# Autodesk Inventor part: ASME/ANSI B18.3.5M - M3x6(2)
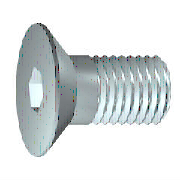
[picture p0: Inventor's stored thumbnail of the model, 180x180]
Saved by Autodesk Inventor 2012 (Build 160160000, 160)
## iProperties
Created: 2011-02
Part Number: ASME/ANSI B18.3.5M - M3x6(2)
Material: Steel, Mild
Description: Broached Hexagon Socket Flat Countersunk Head Cap Screws - Metric
Document SubType Name: Modeling
Standard: ASME/ANSI B18.3.5M
Designer: jrr70267
Standard Revision: 1986
Standards Organization: ANSI
Language: en-US
Size Designation: M3x6
Categories: <MemberInstance><Categories><Category DisplayName="Fasteners" InternalName="e4da775c-781d-43d5-af7c-5136215cf5a6" Mnemonic="FSTN"><Category DisplayName="Bolts"
Density: 7.86 g/cm^3
IsCustomPart: 0
Author: jrr70267
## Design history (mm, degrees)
sketch "Sketch2"
  geometry: L1 (0, -6)-(-1.5, -6); L2 (0, 0)-(0, -6); L3 (-2.675, 0)-(0, 0); L4 (-2.675, -0.685)-(-2.675, 0); L5 (-1.5, -1.86)-(-2.675, -0.685); L6 (-1.5, -6)-(-1.5, -1.86); L7 (0, 0)-(0, -6); 1 further point
  constraints: 14 end point, 3 vertical, 2 horizontal, 1 coincident
  dimensions: "d2" = 45 deg angle of L5 L2; "d4" = 1.5 distance of L1.start L1.end (= 0.5 x NND); "d6" = 2.675 distance of L3.start L2.start (= 0.5 x ParA); "d8" = 1.86 vertical distance of L2.start L5.start (= ParH); "d10" = 6 distance of L2.start L1.start (= NLG)
fillet "Fillet1" dims "d24" = 0.25 (= Rr)
chamfer "Chamfer1" distance "d25" = 0.25 (= 0.5 x PTC); stored, may be unused: second distance "d26" = 0.25 (= 0.5 x PTC), angle "d41" = 45 deg
sketch "Sketch4"
  geometry: L1 (-1, -0.577)-(-1, 0.577); L2 (-1, 0.577)-(0, 1.155); L3 (0, 1.155)-(1, 0.577); L4 (1, 0.577)-(1, -0.577); L5 (1, -0.577)-(0, -1.155); L6 (0, -1.155)-(-1, -0.577); C1 r 2.675 at (0, 0) reference; C2 r 1 at (0, 0)
  constraints: 12 end point, 6 tangent, 4 equal length, 1 centre point, 1 coincident, 1 parallel, 1 vertical
  dimensions: "d27" = 2 diameter of C2 (= ParJ)
extrude "Extrusion2" cut sketch "Sketch4" distance "d39" = 1.1 (= Tt); taper "d40" = 0 deg
node "MSC_A1"
node "MSC_PF1"
node "MSC_PT1"
body "Solid1"
revolve "Revolution1" stored, may be unused: angle "d11" = 360 deg
extrude "Extrusion1" cut sketch "Sketch4" distance "d28" = 1.1 (= Tt); taper "d29" = 0 deg
thread "Thread1" dims "d31" = 3.14 (= Lt), "d32" = 0
sketch "Sketch5"
  geometry: C1 r 2.675 at (0, 0) reference; C2 r 1.01 at (0, 0)
  constraints: 1 centre point, 1 coincident
  dimensions: "d38" = 2.02 diameter of C2 (= 1.01 x ParJ)
other parameters: "NND" = 3 [user parameter; used in 2 equation terms], "NLG" = 6 [user parameter; used in 1 equation term], "PTC" = 0.5 [user parameter; used in 2 equation terms], "ParA" = 5.35 [user parameter; used in 1 equation term], "ParH" = 1.86 [user parameter; used in 1 equation term], "ParJ" = 2 [user parameter; used in 3 equation terms], "Tt" = 1.1 [user parameter; used in 2 equation terms], "Rr" = 0.25 [user parameter; used in 1 equation term], "msp_e" = 0.57735 (= 0.288675 x ParJ) [user parameter], "d1" = 40 deg (derived), "d3" = 9 (derived), "d5" = 14 (derived), "d7" = 8 (derived), "d14" = 0 (derived), "d16" = 120 deg (derived), "d18" = 120 deg (derived), "d19" = 120 deg (derived), "d20" = 5.7735 (derived), "d21" = 14.6647 (derived), "d34" = 0, "d42" = 0, "d43" = 0, "d44" = 0, "Lt" = 3.14 [user parameter; used in 1 equation term], "THREADDIA" = 3 (= NND) [user parameter]
